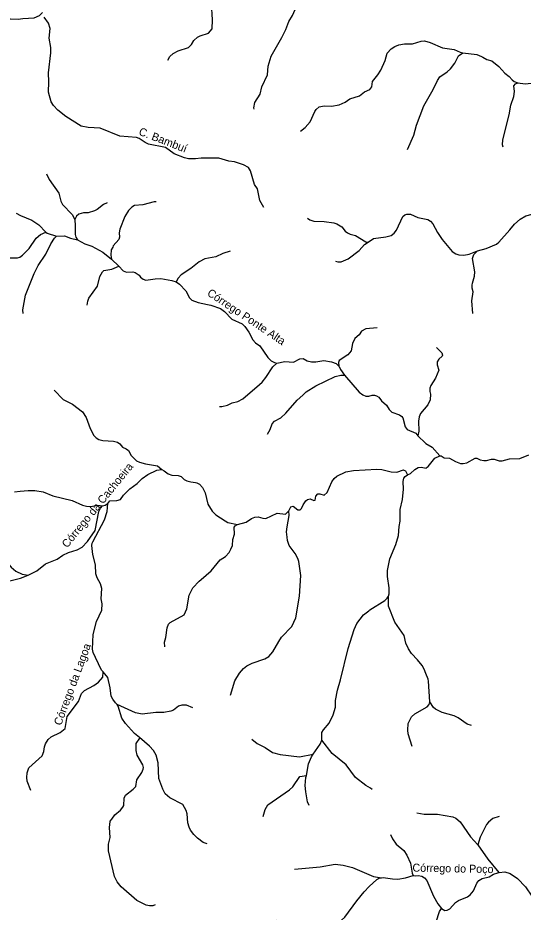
# Model space of a CAD drawing. Extents: x 473.9 to 500, y 7733.1 to 7760.8.
# Drawn here: x 487.45 to 492.5, y 7739.47 to 7748.41 of the extents above; entities that cross this region are included whole.
import ezdxf
from ezdxf.enums import TextEntityAlignment as Align

# ---------------------------------------------------------------- set-up
doc = ezdxf.new("R2010")
doc.units = 0
doc.header["$LTSCALE"] = 0.032
doc.layers.add('61', color=7, linetype='Continuous')
doc.layers.add('7', color=7, linetype='Continuous', lineweight=25)

msp = doc.modelspace()

# ---------------------------------------------------------------- linework, layer by layer
at = {"layer": '7'}
msp.add_line((488.3888, 7745.994), (488.4621, 7745.926), dxfattribs=at)
for points in [[(488.9484, 7747.9844), (488.9713, 7748.0211), (489.0022, 7748.0511), (489.0516, 7748.0781), (489.1553, 7748.1088), (489.1871, 7748.1399), (489.2107, 7748.1811), (489.2464, 7748.2122), (489.2732, 7748.2263), (489.3574, 7748.2526), (489.3939, 7748.2965), (489.3956, 7748.3857), (489.3844, 7748.554), (489.3636, 7748.6764), (489.3644, 7748.7832), (489.407, 7748.9372), (489.4664, 7749.0481), (489.5109, 7749.12), (489.5501, 7749.1833)], [(489.8103, 7747.494), (489.8078, 7747.506), (489.818, 7747.562), (489.873, 7747.6434), (489.8883, 7747.716), (489.9461, 7747.8383), (489.9513, 7747.9247), (489.9823, 7748.0223), (490.0887, 7748.2095), (490.1271, 7748.2896), (490.1564, 7748.369), (490.1952, 7748.4305), (490.2476, 7748.5514), (490.3203, 7748.6421), (490.3273, 7748.6595), (490.328, 7748.6918), (490.3282, 7748.6999), (490.341, 7748.738), (490.3882, 7748.7805), (490.4292, 7748.8038), (490.4871, 7748.817), (490.524, 7748.8333)], [(487.0191, 7748.2502), (487.0804, 7748.2965), (487.2027, 7748.3564), (487.2773, 7748.3661), (487.3794, 7748.3957), (487.4572, 7748.3934), (487.5013, 7748.4013), (487.615, 7748.4076), (487.6676, 7748.4312), (487.7, 7748.4595)], [(489.9071, 7746.5133), (489.8675, 7746.582), (489.8446, 7746.6993), (489.8156, 7746.7407), (489.7753, 7746.8789), (489.754, 7746.91), (489.7045, 7746.9392), (489.6455, 7746.9591), (489.6153, 7746.9693), (489.5586, 7746.9742), (489.4595, 7747.0039), (489.2835, 7747.0045), (489.2278, 7746.9965), (489.1551, 7746.9982), (489.1156, 7747.0077), (489.0148, 7747.0485), (488.9277, 7747.1119), (488.7581, 7747.1429), (488.7235, 7747.1598), (488.6636, 7747.2018), (488.6365, 7747.2116), (488.472, 7747.2259), (488.276, 7747.303), (488.1561, 7747.311), (488.0842, 7747.326), (487.9331, 7747.4213), (487.8504, 7747.4851), (487.8081, 7747.5322), (487.7863, 7747.5677), (487.7585, 7747.6631), (487.7624, 7747.7685), (487.7569, 7747.8567), (487.7809, 7748.057), (487.7808, 7748.1094), (487.7657, 7748.2046), (487.7744, 7748.2991), (487.7596, 7748.3542), (487.7145, 7748.4138)], [(490.2744, 7747.2744), (490.3199, 7747.3123), (490.3716, 7747.3689), (490.4176, 7747.47), (490.432, 7747.4918), (490.4613, 7747.5185), (490.5095, 7747.529), (490.5833, 7747.5242), (490.6618, 7747.5368), (490.72, 7747.565), (490.7665, 7747.5977), (490.8632, 7747.627), (490.9149, 7747.6659), (490.9651, 7747.6899), (490.988, 7747.7185), (490.9949, 7747.7703), (491.0475, 7747.8363), (491.0758, 7747.8824), (491.1184, 7747.9806), (491.1405, 7748.0536), (491.1783, 7748.0979), (491.2147, 7748.1218), (491.2558, 7748.1375), (491.3116, 7748.1463), (491.3921, 7748.1472), (491.4804, 7748.1752), (491.5126, 7748.176), (491.5688, 7748.1607), (491.6926, 7748.1072), (491.8087, 7748.0895), (491.8671, 7748.0629), (491.8957, 7748.0582)], [(491.3436, 7747.0906), (491.4057, 7747.2355), (491.4325, 7747.3359), (491.5074, 7747.5272), (491.5991, 7747.6904), (491.6407, 7747.7791), (491.666, 7747.8165), (491.7379, 7747.8667), (491.7719, 7747.8976), (491.8158, 7747.9545), (491.8515, 7748.0261), (491.8957, 7748.0582)], [(491.8957, 7748.0582), (492.0363, 7748.0402), (492.0829, 7748.0206), (492.096, 7748.0126), (492.1333, 7747.9897), (492.1861, 7747.977), (492.2543, 7747.9215), (492.3147, 7747.8532), (492.3561, 7747.8214), (492.389, 7747.7861), (492.4075, 7747.7718), (492.4457, 7747.7561)], [(492.2962, 7747.1155), (492.29, 7747.1365), (492.2958, 7747.1893), (492.3575, 7747.4379), (492.3734, 7747.5335), (492.4053, 7747.6214), (492.4119, 7747.6707), (492.4047, 7747.7259), (492.4195, 7747.7466), (492.4457, 7747.7561)], [(492.4457, 7747.7561), (492.5181, 7747.747), (492.6746, 7747.7647), (492.7266, 7747.7647), (492.7605, 7747.7553), (492.877, 7747.723), (492.8969, 7747.7124), (492.9769, 7747.6113), (492.9991, 7747.5996), (493.0428, 7747.5948), (493.1871, 7747.6114), (493.2375, 7747.5933), (493.3391, 7747.5393), (493.4074, 7747.522)], [(487.7371, 7746.8487), (487.7666, 7746.7914), (487.8601, 7746.6537), (487.8831, 7746.5739), (487.8991, 7746.5408), (487.9963, 7746.442), (488.0212, 7746.391)], [(488.3445, 7746.5577), (488.3077, 7746.5426), (488.2447, 7746.4923), (488.2164, 7746.4776), (488.155, 7746.4592), (488.1083, 7746.4579), (488.06, 7746.4457), (488.0397, 7746.4259), (488.0212, 7746.391)], [(488.8345, 7746.5675), (488.8132, 7746.5676), (488.7019, 7746.5381), (488.6182, 7746.53), (488.5906, 7746.5163), (488.5585, 7746.4832), (488.519, 7746.4227), (488.4694, 7746.2936), (488.4631, 7746.2601), (488.468, 7746.2138), (488.4618, 7746.1906), (488.4056, 7746.1277), (488.4002, 7746.1169), (488.3858, 7746.0884), (488.3823, 7746.0365), (488.3888, 7745.994)], [(492.0417, 7746.0779), (492.1297, 7746.1018), (492.2309, 7746.1456), (492.2541, 7746.1653), (492.3629, 7746.2896), (492.4114, 7746.345), (492.4672, 7746.3936), (492.5235, 7746.4289), (492.5864, 7746.4441), (492.7282, 7746.4627), (492.8558, 7746.4882), (492.8822, 7746.4882), (492.9453, 7746.4646), (492.9856, 7746.4371), (493.0345, 7746.4142), (493.1262, 7746.3936), (493.1905, 7746.39)], [(487.4365, 7746.4549), (487.4787, 7746.4305), (487.5926, 7746.3836), (487.6609, 7746.3373), (487.7328, 7746.2653)], [(488.0212, 7746.391), (488.0233, 7746.3284), (488.0263, 7746.2422), (488.0311, 7746.2144), (488.0486, 7746.1875)], [(490.3457, 7746.4042), (490.3661, 7746.3884), (490.4069, 7746.3762), (490.5092, 7746.3712), (490.6063, 7746.3592), (490.6387, 7746.3486), (490.6877, 7746.3171), (490.7215, 7746.2763), (490.7441, 7746.2587), (490.7689, 7746.2457), (490.8231, 7746.2308), (490.9266, 7746.1691), (490.9514, 7746.1647)], [(490.9514, 7746.1647), (491.0018, 7746.2032), (491.1263, 7746.2173), (491.1782, 7746.2311), (491.2097, 7746.2562), (491.2319, 7746.2857), (491.2961, 7746.4228), (491.3147, 7746.4398), (491.3347, 7746.4466), (491.3741, 7746.4442), (491.4467, 7746.4103), (491.5441, 7746.3913), (491.5736, 7746.375), (491.5969, 7746.3481), (491.6437, 7746.2624), (491.6897, 7746.193), (491.7876, 7746.0735), (491.8247, 7746.0491), (491.8541, 7746.0397), (491.9059, 7746.0369), (491.9594, 7746.0441), (492.0417, 7746.0779)], [(486.9514, 7745.0862), (486.9552, 7745.1044), (486.974, 7745.1325), (487.0331, 7745.206), (487.0468, 7745.2802), (487.0879, 7745.3684), (487.1077, 7745.447), (487.1489, 7745.5419), (487.1731, 7745.6287), (487.1825, 7745.7223), (487.2003, 7745.7808), (487.2004, 7745.858), (487.2104, 7745.9056), (487.2323, 7745.9524), (487.2728, 7745.9865), (487.3399, 7746.0096), (487.4483, 7746.0089), (487.4707, 7746.0142), (487.5, 7746.0343), (487.565, 7746.1024), (487.6346, 7746.2048), (487.6801, 7746.2431), (487.7328, 7746.2653)], [(487.504, 7745.4526), (487.5027, 7745.4895), (487.5283, 7745.6349), (487.616, 7745.8538), (487.6554, 7745.9325), (487.7311, 7746.0457), (487.7834, 7746.1489), (487.8188, 7746.2063), (487.8385, 7746.2261)], [(487.7328, 7746.2653), (487.7452, 7746.2558), (487.8385, 7746.2261)], [(487.8385, 7746.2261), (487.9171, 7746.2293), (487.9768, 7746.2059), (488.0486, 7746.1875)], [(488.0486, 7746.1875), (488.1211, 7746.1482), (488.1903, 7746.1262), (488.3014, 7746.0661), (488.3888, 7745.994)], [(490.6242, 7745.9767), (490.6465, 7745.9691), (490.6815, 7745.9703), (490.749, 7745.9992), (490.8611, 7746.0831), (490.9137, 7746.1413), (490.9514, 7746.1647)], [(489.5717, 7746.0742), (489.4986, 7746.053), (489.4306, 7746.0193), (489.3206, 7745.9993), (489.262, 7745.9675), (489.181, 7745.9031), (489.0837, 7745.8387), (489.0823, 7745.8373), (489.0529, 7745.8068), (489.0326, 7745.7685)], [(491.9944, 7745.4509), (491.9846, 7745.5802), (491.9967, 7745.67), (491.9878, 7745.7044), (491.9871, 7745.7372), (491.9919, 7745.7549), (492.011, 7745.8257), (492.0141, 7745.8698), (491.9927, 7746.0029), (492.0057, 7746.041), (492.0417, 7746.0779)], [(488.1458, 7745.5357), (488.1497, 7745.577), (488.1606, 7745.6041), (488.2479, 7745.7241), (488.2723, 7745.8212), (488.2963, 7745.8687), (488.3125, 7745.8837), (488.3907, 7745.8971), (488.4621, 7745.926)], [(488.4621, 7745.926), (488.5037, 7745.88), (488.5368, 7745.8644), (488.5993, 7745.8686), (488.623, 7745.8628), (488.6639, 7745.8367), (488.6785, 7745.8159), (488.7048, 7745.7947), (488.7317, 7745.7844), (488.8236, 7745.7988), (488.8793, 7745.8011), (488.9888, 7745.7822), (489.0326, 7745.7685)], [(489.0326, 7745.7685), (489.0666, 7745.7467), (489.1294, 7745.6776), (489.1667, 7745.6085), (489.1896, 7745.5868), (489.2542, 7745.5615), (489.3457, 7745.5439), (489.3793, 7745.5374), (489.4755, 7745.5022), (489.5154, 7745.4738), (489.5882, 7745.3958), (489.691, 7745.3495), (489.7201, 7745.322), (489.7596, 7745.2663), (489.7994, 7745.1889), (489.8252, 7745.1607), (489.8681, 7745.1282), (489.9472, 7745.0135), (489.9815, 7744.9789), (490.0134, 7744.9616), (490.0381, 7744.9575)], [(491.0404, 7745.3081), (490.9257, 7745.299), (490.8844, 7745.2774), (490.8595, 7745.2405), (490.8158, 7745.2017), (490.7921, 7745.1519), (490.7795, 7745.0783), (490.7482, 7745.038), (490.6612, 7744.9813), (490.6545, 7744.9619), (490.657, 7744.9269)], [(491.6326, 7745.1112), (491.6861, 7745.0581), (491.691, 7745.0367), (491.6887, 7745.0261), (491.6539, 7744.995), (491.6402, 7744.9708), (491.6385, 7744.9392), (491.6565, 7744.8848), (491.6224, 7744.8048), (491.5751, 7744.7318), (491.5661, 7744.7054), (491.5653, 7744.6724), (491.5718, 7744.6462), (491.5682, 7744.589), (491.5446, 7744.5402), (491.4721, 7744.4534), (491.4584, 7744.4191), (491.4514, 7744.3775), (491.4546, 7744.2751), (491.447, 7744.2305)], [(489.4667, 7744.5238), (489.4902, 7744.522), (489.5442, 7744.5365), (489.5924, 7744.5612), (489.6496, 7744.5723), (489.7001, 7744.5991), (489.8637, 7744.7441), (489.8903, 7744.7676), (489.9282, 7744.8115), (489.9972, 7744.9179), (490.0381, 7744.9575)], [(490.0381, 7744.9575), (490.1169, 7744.9713), (490.2043, 7744.9664), (490.2664, 7744.9985), (490.3, 7745.0017), (490.3424, 7744.9807), (490.3831, 7744.969), (490.4287, 7744.9698), (490.5076, 7744.9817), (490.5844, 7744.97), (490.6309, 7744.9542), (490.657, 7744.9269)], [(490.657, 7744.9269), (490.6593, 7744.9221), (490.6739, 7744.8913), (490.7142, 7744.8367)], [(489.9455, 7744.2458), (489.972, 7744.2928), (489.9923, 7744.351), (490.0165, 7744.3774), (490.0769, 7744.4099), (490.1264, 7744.4567), (490.2413, 7744.5878), (490.2964, 7744.6366), (490.3321, 7744.6682), (490.427, 7744.7288), (490.6201, 7744.8235), (490.6782, 7744.8366), (490.7142, 7744.8367)], [(490.7142, 7744.8367), (490.8608, 7744.665), (490.8975, 7744.639), (490.9283, 7744.6266), (490.9565, 7744.6263), (490.9893, 7744.6376), (491.0117, 7744.6362), (491.0316, 7744.6312), (491.0567, 7744.6154), (491.082, 7744.5808), (491.1345, 7744.5362), (491.1611, 7744.4941), (491.1869, 7744.4679), (491.2621, 7744.4413), (491.2848, 7744.4243), (491.2975, 7744.4086), (491.3193, 7744.3215), (491.3389, 7744.2932), (491.4244, 7744.2582), (491.447, 7744.2305)], [(487.8153, 7744.6864), (487.9062, 7744.594), (487.9995, 7744.5473), (488.0977, 7744.47), (488.134, 7744.4126), (488.1731, 7744.3021), (488.2115, 7744.2321), (488.2337, 7744.2103), (488.2602, 7744.1949), (488.3017, 7744.1848), (488.4065, 7744.1759), (488.4466, 7744.1653), (488.4699, 7744.1498), (488.4985, 7744.1174), (488.5345, 7744.1005), (488.5564, 7744.0827), (488.5842, 7744.0331), (488.6375, 7743.9815), (488.667, 7743.9653), (488.7263, 7743.9499), (488.8475, 7743.9297), (488.8898, 7743.8924)], [(491.447, 7744.2305), (491.5226, 7744.1563), (491.5264, 7744.154), (491.588, 7744.1164), (491.6647, 7744.0305)], [(491.3428, 7743.8413), (491.3716, 7743.8544), (491.4171, 7743.8937), (491.4495, 7743.9128), (491.4787, 7743.9161), (491.5274, 7743.9077), (491.5298, 7743.9095), (491.5479, 7743.9229), (491.6155, 7744.0073), (491.6647, 7744.0305)], [(491.6647, 7744.0305), (491.6792, 7744.0292), (491.7091, 7744.0113), (491.7625, 7744.0074), (491.8205, 7743.9729), (491.8712, 7743.9539), (491.8991, 7743.9523), (491.9354, 7743.9601), (492.0175, 7744.0067), (492.0349, 7744.006), (492.0679, 7743.9897), (492.1037, 7743.9829), (492.1317, 7743.9836), (492.1819, 7743.9978), (492.2083, 7743.9963), (492.2593, 7743.9796), (492.2872, 7743.9797), (492.3622, 7744.0003), (492.4652, 7744.002), (492.5527, 7744.0411)], [(488.3494, 7743.5542), (488.3717, 7743.5807), (488.4415, 7743.5827), (488.4762, 7743.5947), (488.5086, 7743.6385), (488.5712, 7743.6994), (488.645, 7743.7548), (488.6497, 7743.7597), (488.693, 7743.8046), (488.7487, 7743.8448), (488.8396, 7743.8866), (488.8898, 7743.8924)], [(488.8898, 7743.8924), (488.9143, 7743.8809), (488.954, 7743.8488), (488.9895, 7743.8382), (489.0525, 7743.8335), (489.0815, 7743.8222), (489.1144, 7743.7948), (489.1411, 7743.7811), (489.1787, 7743.7692), (489.2269, 7743.7631), (489.2402, 7743.7614), (489.2659, 7743.7485), (489.2974, 7743.7147), (489.3243, 7743.6596), (489.3499, 7743.5482), (489.3914, 7743.4771), (489.4287, 7743.442), (489.5214, 7743.3793), (489.5492, 7743.365), (489.6443, 7743.3451)], [(490.1595, 7743.4818), (490.1766, 7743.5207), (490.2027, 7743.5273), (490.2469, 7743.4922), (490.2718, 7743.492), (490.2853, 7743.5054), (490.3007, 7743.5422), (490.3271, 7743.5808), (490.3427, 7743.5938), (490.3705, 7743.5995), (490.4059, 7743.5851), (490.422, 7743.5878), (490.4284, 7743.6272), (490.4467, 7743.6492), (490.469, 7743.6522), (490.5107, 7743.638), (490.5421, 7743.6637), (490.586, 7743.7696), (490.6109, 7743.8029), (490.6368, 7743.8271), (490.7273, 7743.8706), (490.8036, 7743.8849), (491.0365, 7743.8977), (491.0849, 7743.8944), (491.1785, 7743.8689), (491.2372, 7743.8657), (491.302, 7743.8896), (491.306, 7743.8876), (491.322, 7743.8794), (491.3428, 7743.8413)], [(491.1539, 7742.6279), (491.1611, 7742.6518), (491.1611, 7742.711), (491.1436, 7742.8238), (491.1436, 7742.8854), (491.1653, 7742.9996), (491.2276, 7743.1445), (491.2517, 7743.2347), (491.259, 7743.3257), (491.271, 7743.377), (491.2711, 7743.4935), (491.2925, 7743.5947), (491.3039, 7743.698), (491.2992, 7743.7753), (491.3069, 7743.8081), (491.3185, 7743.8249), (491.3428, 7743.8413)], [(487.4196, 7743.6711), (487.4771, 7743.677), (487.5563, 7743.6852), (487.6237, 7743.6844), (487.7049, 7743.6717), (487.8022, 7743.6311), (487.9952, 7743.5831), (488.0989, 7743.5365), (488.1381, 7743.5258), (488.1824, 7743.5234), (488.2518, 7743.537), (488.2972, 7743.5291)], [(487.5561, 7742.838), (487.6408, 7742.8822), (487.7285, 7742.9527), (487.8457, 7742.9992), (487.9009, 7743.0362), (487.9588, 7743.0654), (488.0461, 7743.0906), (488.0953, 7743.1191), (488.1455, 7743.1704), (488.1485, 7743.1735), (488.2242, 7743.2827), (488.2616, 7743.474), (488.2789, 7743.5078), (488.2972, 7743.5291)], [(488.3053, 7741.8714), (488.288, 7741.8901), (488.2281, 7742.0162), (488.206, 7742.0637), (488.1981, 7742.0996), (488.2043, 7742.244), (488.2369, 7742.3738), (488.2904, 7742.4886), (488.2956, 7742.5515), (488.2845, 7742.6025), (488.2924, 7742.7042), (488.2782, 7742.7497), (488.2445, 7742.8127), (488.2315, 7742.8514), (488.2282, 7742.9416), (488.2011, 7743.0435), (488.1898, 7743.134), (488.1947, 7743.156), (488.2022, 7743.1703), (488.3185, 7743.3914), (488.3437, 7743.4752), (488.3494, 7743.5542)], [(488.2972, 7743.5291), (488.3242, 7743.5377), (488.3494, 7743.5542)], [(489.5748, 7741.6374), (489.6181, 7741.7813), (489.6639, 7741.8594), (489.7057, 7741.9067), (489.7386, 7741.9313), (489.7933, 7741.9582), (489.9187, 7742.0017), (489.9572, 7742.0262), (489.9988, 7742.0715), (490.0595, 7742.1748), (490.0857, 7742.2193), (490.1891, 7742.3256), (490.2288, 7742.4113), (490.2656, 7742.6269), (490.2761, 7742.833), (490.2568, 7742.9729), (490.2477, 7743.0028), (490.2216, 7743.0531), (490.1604, 7743.1339), (490.1446, 7743.183), (490.1407, 7743.218), (490.135, 7743.2695), (490.1398, 7743.3219), (490.1622, 7743.4339), (490.1595, 7743.4818)], [(489.6443, 7743.3451), (489.7321, 7743.3676), (489.7859, 7743.405), (489.8178, 7743.4183), (489.8507, 7743.4198), (489.8971, 7743.4068), (489.9283, 7743.4055), (490.0413, 7743.4566), (490.1233, 7743.4487), (490.1595, 7743.4818)], [(488.9194, 7742.1202), (488.9156, 7742.1673), (488.9298, 7742.2145), (488.9446, 7742.3126), (488.9577, 7742.348), (488.9737, 7742.3661), (489.114, 7742.4406), (489.1393, 7742.5012), (489.1621, 7742.6375), (489.1991, 7742.7112), (489.264, 7742.7775), (489.2833, 7742.7943), (489.3816, 7742.8797), (489.474, 7742.9899), (489.5273, 7743.0256), (489.5631, 7743.0656), (489.5784, 7743.0985), (489.5956, 7743.1356), (489.5986, 7743.1934), (489.6153, 7743.2488), (489.6137, 7743.316), (489.6237, 7743.3309), (489.6443, 7743.3451)], [(486.8241, 7743.0156), (486.9234, 7743.0132), (487.0413, 7743.047), (487.0983, 7743.048), (487.146, 7743.018), (487.1898, 7742.9996), (487.3129, 7742.9884), (487.3397, 7742.971), (487.3862, 7742.9165), (487.4319, 7742.8783), (487.4957, 7742.8481), (487.5561, 7742.838)], [(486.9771, 7742.4003), (487.045, 7742.539), (487.0859, 7742.6079), (487.1266, 7742.6614), (487.167, 7742.6939), (487.245, 7742.7315), (487.3216, 7742.7566), (487.3729, 7742.7822), (487.4788, 7742.8085), (487.5561, 7742.838)], [(490.4861, 7741.1875), (490.4867, 7741.2659), (490.5032, 7741.294), (490.5598, 7741.3602), (490.5997, 7741.4412), (490.6223, 7741.5189), (490.6231, 7741.5862), (490.6437, 7741.6877), (490.6753, 7741.7931), (490.7506, 7742.1054), (490.809, 7742.2959), (490.8364, 7742.3543), (490.9036, 7742.4415), (490.9561, 7742.4817), (490.9674, 7742.4903), (491.1165, 7742.5854), (491.1412, 7742.6069), (491.1539, 7742.6279)], [(491.567, 7741.5737), (491.554, 7741.777), (491.5475, 7741.7997), (491.5252, 7741.8561), (491.5078, 7741.8999), (491.4885, 7741.9339), (491.4436, 7741.9917), (491.3824, 7742.0544), (491.3528, 7742.101), (491.3245, 7742.1577), (491.3078, 7742.2359), (491.2162, 7742.3677), (491.1536, 7742.5276), (491.1539, 7742.6279)], [(487.5825, 7740.6874), (487.5472, 7740.778), (487.5412, 7740.8174), (487.5444, 7740.8632), (487.5633, 7740.9132), (487.694, 7741.0319), (487.7136, 7741.0749), (487.7184, 7741.123), (487.7277, 7741.151), (487.7568, 7741.1957), (487.7866, 7741.2216), (487.8757, 7741.2648), (487.9254, 7741.3066), (487.9462, 7741.4261), (488.0569, 7741.5755), (488.087, 7741.6549), (488.1169, 7741.6846), (488.2122, 7741.7338), (488.2585, 7741.7672), (488.3012, 7741.8179), (488.3053, 7741.8714)], [(488.4439, 7741.5439), (488.4284, 7741.5633), (488.4, 7741.5988), (488.3837, 7741.6293), (488.3735, 7741.712), (488.3508, 7741.8142), (488.3053, 7741.8714)], [(488.6687, 7741.2142), (488.6188, 7741.2541), (488.5259, 7741.355), (488.4922, 7741.408), (488.455, 7741.53), (488.4439, 7741.5439)], [(489.1988, 7741.5129), (489.1355, 7741.5373), (489.0883, 7741.5405), (489.0563, 7741.5279), (489.0058, 7741.4884), (488.9809, 7741.4785), (488.9103, 7741.466), (488.829, 7741.4643), (488.6923, 7741.4499), (488.6278, 7741.4626), (488.4439, 7741.5439)], [(491.3888, 7741.1242), (491.3497, 7741.2539), (491.3456, 7741.2891), (491.3505, 7741.3556), (491.3829, 7741.4232), (491.4151, 7741.4518), (491.5394, 7741.5235), (491.5576, 7741.5461), (491.567, 7741.5737)], [(491.9813, 7741.3345), (491.9375, 7741.349), (491.8485, 7741.4108), (491.8091, 7741.4315), (491.6878, 7741.4657), (491.6224, 7741.5004), (491.6036, 7741.5159), (491.567, 7741.5737)], [(488.8219, 7739.5432), (488.7997, 7739.535), (488.7664, 7739.533), (488.7331, 7739.5406), (488.6403, 7739.587), (488.4826, 7739.7248), (488.4449, 7739.7728), (488.4186, 7739.8259), (488.3566, 7740.083), (488.3582, 7740.1497), (488.3741, 7740.2151), (488.3661, 7740.3157), (488.3741, 7740.3748), (488.3748, 7740.3798), (488.3904, 7740.4005), (488.4223, 7740.4428), (488.4758, 7740.4899), (488.5002, 7740.5193), (488.5102, 7740.5363), (488.5138, 7740.608), (488.5267, 7740.6384), (488.6054, 7740.7004), (488.6289, 7740.7272), (488.6389, 7740.7943), (488.6902, 7740.8673), (488.7034, 7740.8981), (488.7062, 7740.9171), (488.7006, 7740.9415), (488.6441, 7741.04), (488.6324, 7741.0868), (488.6354, 7741.1542), (488.67, 7741.2085), (488.6687, 7741.2142)], [(489.3431, 7740.1516), (489.3034, 7740.1682), (489.2452, 7740.2093), (489.2083, 7740.2462), (489.1772, 7740.2911), (489.1613, 7740.32), (489.1488, 7740.3623), (489.1439, 7740.4524), (489.1346, 7740.485), (489.0987, 7740.5463), (488.9692, 7740.6114), (488.9246, 7740.6528), (488.8986, 7740.6994), (488.8585, 7740.8065), (488.852, 7740.9611), (488.8343, 7741.0396), (488.8077, 7741.0845), (488.7676, 7741.1302), (488.6687, 7741.2142)], [(489.7869, 7741.1992), (489.8428, 7741.155), (489.9203, 7741.117), (489.9965, 7741.0673), (490.0702, 7741.0446), (490.2637, 7741.0233), (490.4022, 7741.0493)], [(490.4022, 7741.0493), (490.4723, 7741.1481), (490.4861, 7741.1875)], [(490.9901, 7740.6965), (490.9748, 7740.7107), (490.9254, 7740.7375), (490.8245, 7740.8172), (490.7304, 7740.9418), (490.592, 7741.0569), (490.4861, 7741.1875)], [(490.3343, 7740.8367), (490.3531, 7740.9534), (490.3833, 7741.0215), (490.4022, 7741.0493)], [(489.9023, 7740.4251), (489.9226, 7740.4976), (489.9497, 7740.5429), (490.165, 7740.6919), (490.1964, 7740.724), (490.2668, 7740.8268), (490.3343, 7740.8367)], [(490.3594, 7740.5361), (490.3459, 7740.5743), (490.3264, 7740.6731), (490.321, 7740.7368), (490.3274, 7740.8164), (490.3343, 7740.8367)], [(491.4349, 7740.4633), (491.5076, 7740.4485), (491.6407, 7740.4485), (491.7947, 7740.4237), (491.8267, 7740.4108), (491.8684, 7740.374), (491.9726, 7740.2216), (492.0454, 7740.142)], [(492.2588, 7740.427), (492.1955, 7740.4058), (492.1498, 7740.3691), (492.1318, 7740.3456), (492.0683, 7740.2209), (492.0454, 7740.142)], [(491.1714, 7740.2454), (491.1913, 7740.2033), (491.2291, 7740.1497), (491.3065, 7740.0858), (491.3374, 7740.039), (491.3732, 7739.959), (491.3897, 7739.8588), (491.3995, 7739.8352)], [(492.0454, 7740.142), (492.1458, 7740.0003), (492.2531, 7739.8665), (492.2536, 7739.8659)], [(490.2131, 7739.8993), (490.4707, 7739.925), (490.621, 7739.9489), (490.7009, 7739.9401), (490.7938, 7739.918), (491.0049, 7739.8252), (491.084, 7739.815)], [(491.683, 7739.5064), (491.7157, 7739.4877), (491.7395, 7739.4899), (491.7663, 7739.5037), (491.8216, 7739.5671), (491.8513, 7739.5869), (491.9415, 7739.6231), (491.9696, 7739.6422), (492.0003, 7739.6821), (492.0337, 7739.7616), (492.0562, 7739.7867), (492.089, 7739.8052), (492.1567, 7739.8229), (492.2022, 7739.8496), (492.2442, 7739.8649), (492.2536, 7739.8659)], [(492.2536, 7739.8659), (492.2587, 7739.8665), (492.3135, 7739.8724), (492.3664, 7739.8554), (492.4413, 7739.8061), (492.5196, 7739.7241), (492.5834, 7739.6301), (492.6616, 7739.5527), (492.7104, 7739.5346), (492.7723, 7739.5322), (492.8039, 7739.5382)], [(490.0364, 7739.3905), (490.1076, 7739.3721), (490.1641, 7739.3732), (490.3094, 7739.3429), (490.4052, 7739.3316), (490.4964, 7739.3316), (490.5852, 7739.3443), (490.6836, 7739.3919), (490.7178, 7739.4189), (490.8371, 7739.5847), (490.9115, 7739.6731), (490.9589, 7739.7258), (491.038, 7739.7976), (491.0653, 7739.8128), (491.084, 7739.815)], [(491.084, 7739.815), (491.1003, 7739.8169), (491.192, 7739.8022), (491.2449, 7739.8015), (491.3222, 7739.812), (491.3995, 7739.8352)], [(491.3995, 7739.8352), (491.4253, 7739.8329), (491.4494, 7739.8383), (491.4874, 7739.8307), (491.5121, 7739.8144), (491.5344, 7739.7864), (491.6035, 7739.6318), (491.6465, 7739.5532), (491.683, 7739.5064)], [(490.5407, 7738.9368), (490.5796, 7738.9151), (490.7432, 7738.8907), (490.7926, 7738.8955), (490.8972, 7738.9275), (490.9755, 7738.9242), (491.0139, 7738.9137), (491.1269, 7738.8556), (491.1986, 7738.8426), (491.3834, 7738.845), (491.4457, 7738.8589), (491.4689, 7738.8746), (491.4744, 7738.8783), (491.5119, 7738.936), (491.5369, 7738.9664), (491.5691, 7738.9915), (491.5702, 7738.9933), (491.5812, 7739.0106), (491.5782, 7739.0996), (491.6273, 7739.3685), (491.628, 7739.3723), (491.6613, 7739.4769), (491.683, 7739.5064)]]:
    msp.add_lwpolyline(points, dxfattribs=at)

# ---------------------------------------------------------------- texts
at = {"layer": '61'}
for s, rotation, p in [('C. Bambuí', 338.888, (488.8883, 7747.1492)), ('Córrego Ponte Alta', 326.121, (489.7128, 7745.386)), ('Córrego da Cachoeira', 50.866, (488.2778, 7743.5125)), ('Córrego da Lagoa', 69.567, (488.0342, 7741.7337)), ('Córrego do Poço', 358.898, (491.7961, 7739.868))]:
    msp.add_text(s, height=0.08, rotation=rotation, dxfattribs=at).set_placement(p, align=Align.CENTER)

doc.saveas('drawing.dxf')
